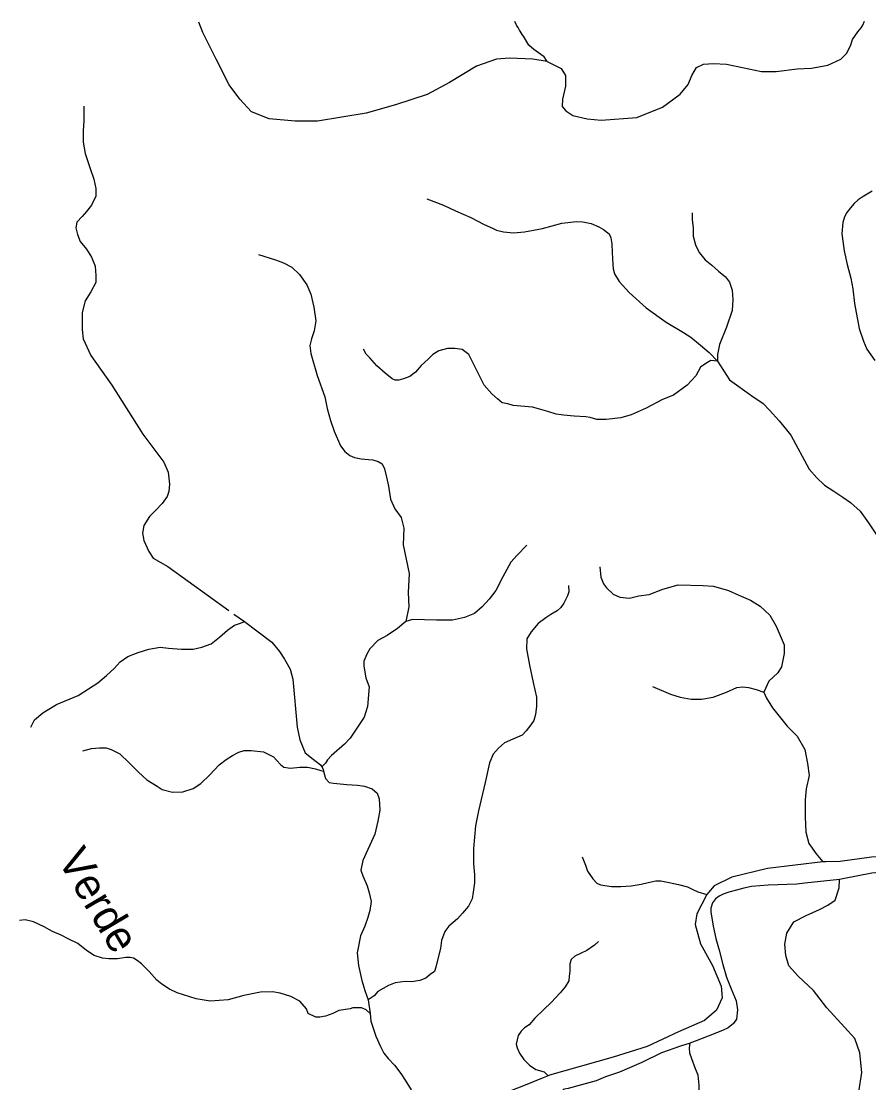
# Model space of a CAD drawing. Extents: x 436.3 to 500.4, y 8231 to 8286.4.
# Drawn here: x 467.97 to 473.38, y 8279.55 to 8286.33 of the extents above; entities that cross this region are included whole.
import ezdxf
from ezdxf.enums import TextEntityAlignment as Align

# ---------------------------------------------------------------- set-up
doc = ezdxf.new("R2010")
doc.units = 0
doc.header["$LTSCALE"] = 0.08
doc.linetypes.add('LONG_DASHED', pattern=[7.5, 6, -1.5])
for name, color, linetype, lineweight in [('2', 7, 'Continuous', 25), ('7', 7, 'Continuous', 25), ('9', 7, 'LONG_DASHED', 25)]:
    doc.layers.add(name, color=color, linetype=linetype, lineweight=lineweight)
doc.layers.add('61', color=7, linetype='Continuous')

msp = doc.modelspace()

# ---------------------------------------------------------------- linework, layer by layer
at = {"layer": '2'}
for points in [[(474.3305, 8281.4045), (474.2809, 8281.3357), (474.1471, 8281.1798), (474.058, 8281.1131), (473.9298, 8281.063), (473.8071, 8281.0295), (473.5859, 8281.0006), (473.4019, 8280.9949), (473.2012, 8280.9669), (473.1097, 8280.965), (473.0916, 8280.9642)], [(474.3152, 8281.2109), (474.2672, 8281.1647), (474.2064, 8281.1116), (474.1321, 8281.0507), (474.0522, 8281.0127), (473.9494, 8280.9767), (473.8485, 8280.9481), (473.6818, 8280.9216), (473.5485, 8280.9044), (473.4038, 8280.8911), (473.2198, 8280.8552), (473.1971, 8280.8509)], [(473.0916, 8280.9642), (472.7382, 8280.9222), (472.5097, 8280.8664), (472.3983, 8280.8106), (472.3612, 8280.7687), (472.3504, 8280.7564)], [(473.1971, 8280.8509), (472.9763, 8280.8278), (472.9249, 8280.822), (472.7422, 8280.8142), (472.6356, 8280.8066), (472.588, 8280.7951), (472.5404, 8280.7837), (472.4909, 8280.7704), (472.4548, 8280.7571), (472.43, 8280.7457)], [(472.3504, 8280.7564), (472.287, 8280.6324), (472.2761, 8280.5632), (472.3097, 8280.4407), (472.388, 8280.3016), (472.4427, 8280.1693), (472.4479, 8280.0954), (472.4123, 8280.0166), (472.3361, 8279.9506), (472.171, 8279.8785), (471.9705, 8279.7838), (471.7531, 8279.717), (471.3466, 8279.6007), (471.3388, 8279.5975)], [(472.43, 8280.7457), (472.4054, 8280.7286), (472.3882, 8280.702), (472.3769, 8280.6678), (472.377, 8280.6454), (472.3904, 8280.5523), (472.4076, 8280.4744)], [(472.4076, 8280.4744), (472.4287, 8280.4003), (472.4536, 8280.3091), (472.4766, 8280.2275), (472.5068, 8280.1521), (472.5374, 8280.0762), (472.5469, 8280.0192), (472.5394, 8279.9585), (472.5222, 8279.9319), (472.4862, 8279.9034), (472.45, 8279.8863), (472.3586, 8279.85), (472.2826, 8279.8205), (472.2536, 8279.8109), (472.2478, 8279.8075), (472.2446, 8279.8065)], [(472.2446, 8279.8065), (472.1836, 8279.7872), (472.0606, 8279.7445), (471.9351, 8279.6818), (471.7925, 8279.6211), (471.7049, 8279.5907), (471.6441, 8279.5659), (471.5508, 8279.5393), (471.4662, 8279.517), (471.4429, 8279.5118), (471.4344, 8279.5086), (471.4339, 8279.5085), (471.4311, 8279.5077)], [(471.3388, 8279.5975), (471.3373, 8279.5969), (471.307, 8279.5845), (471.1919, 8279.5375), (470.9078, 8279.4262), (470.6906, 8279.3427), (470.5717, 8279.309), (470.5428, 8279.3005)]]:
    msp.add_lwpolyline(points, dxfattribs=at)
at = {"layer": '7'}
for points in [[(470.2005, 8279.9953), (470.1763, 8280.0194), (470.1459, 8280.0315), (470.0915, 8280.0315), (470.0733, 8280.0255), (470.0005, 8280.0134), (469.9642, 8279.9953), (469.9157, 8279.9771), (469.8794, 8279.9711), (469.8551, 8279.9711), (469.8066, 8279.9952), (469.7944, 8280.0255), (469.7519, 8280.0739), (469.6959, 8280.1042), (469.6261, 8280.1253), (469.5776, 8280.1344), (469.5019, 8280.1314), (469.3959, 8280.1102), (469.2959, 8280.0829), (469.1809, 8280.0737), (469.0899, 8280.0888), (468.9702, 8280.1281), (468.9207, 8280.1505), (468.8712, 8280.182), (468.8396, 8280.2089), (468.7901, 8280.2629), (468.7406, 8280.3123), (468.7136, 8280.3348), (468.6911, 8280.3483), (468.6686, 8280.3528), (468.6416, 8280.3527), (468.5877, 8280.3437), (468.5337, 8280.3436), (468.4933, 8280.3481), (468.4393, 8280.366), (468.3898, 8280.3975), (468.3358, 8280.4424), (468.2773, 8280.4693), (468.2278, 8280.4963), (468.1738, 8280.5187), (468.1192, 8280.5479), (468.0525, 8280.5811), (467.998, 8280.5933), (467.9616, 8280.5901)], [(470.2005, 8279.9953), (470.2067, 8279.9468), (470.2371, 8279.8499), (470.2675, 8279.7834), (470.2883, 8279.7416), (470.3163, 8279.7073), (470.3558, 8279.6651), (470.3964, 8279.6112), (470.4254, 8279.5694), (470.464, 8279.5078), (470.4911, 8279.4538), (470.5136, 8279.3954), (470.5398, 8279.309), (470.5428, 8279.3005)]]:
    msp.add_lwpolyline(points, dxfattribs=at)
at = {"layer": '9'}
for points in [[(469.1441, 8286.2409), (469.1337, 8286.2631), (469.1073, 8286.3294)], [(471.3308, 8286.0766), (471.3133, 8286.1064), (471.2911, 8286.1229), (471.2468, 8286.1532), (471.2136, 8286.1808), (471.1804, 8286.2386), (471.1728, 8286.2489), (471.1602, 8286.2704), (471.1554, 8286.2775), (471.1454, 8286.295), (471.1385, 8286.3061), (471.1256, 8286.332)], [(471.3308, 8286.0766), (471.4208, 8286.0319), (471.4489, 8285.9879), (471.4489, 8285.919), (471.4284, 8285.8376), (471.4268, 8285.7899), (471.4509, 8285.7629), (471.496, 8285.733), (471.5861, 8285.7105), (471.6762, 8285.703), (471.9035, 8285.7187), (472.0687, 8285.786), (472.1813, 8285.8681), (472.2322, 8285.9307), (472.2543, 8285.9885), (472.2848, 8286.0381), (472.329, 8286.0602), (472.3927, 8286.0656), (472.4757, 8286.0601), (472.5782, 8286.0381), (472.6999, 8286.0133), (472.7941, 8286.0133), (472.9269, 8286.0298), (473.0184, 8286.0353), (473.1235, 8286.0546), (473.2066, 8286.0931), (473.2454, 8286.1317), (473.2703, 8286.184), (473.2813, 8286.217), (473.3145, 8286.2666), (473.3353, 8286.2935), (473.3464, 8286.3089), (473.3579, 8286.3347)], [(471.3308, 8286.0766), (471.2406, 8286.0916), (471.0905, 8286.0991), (471.0079, 8286.0916), (470.8804, 8286.0468), (470.7077, 8285.9423), (470.5652, 8285.8675), (470.3626, 8285.8004), (470.175, 8285.7481), (469.8646, 8285.6958), (469.722, 8285.6958), (469.5569, 8285.7107), (469.4444, 8285.7556), (469.3693, 8285.8377), (469.3018, 8285.9273), (469.2191, 8286.0915), (469.1441, 8286.2409)], [(468.3735, 8285.7916), (468.3736, 8285.6992), (468.3695, 8285.6348), (468.3695, 8285.5625), (468.3818, 8285.4901), (468.4141, 8285.3936), (468.4383, 8285.3252), (468.4504, 8285.265), (468.4504, 8285.2167), (468.4223, 8285.1604), (468.39, 8285.1201), (468.3618, 8285.088), (468.3294, 8285.0518), (468.3215, 8285.0155), (468.3336, 8284.9712), (468.3497, 8284.9271), (468.3901, 8284.8787), (468.4225, 8284.8265), (468.4467, 8284.7701), (468.4508, 8284.7098), (468.4508, 8284.6655), (468.4186, 8284.6051), (468.3824, 8284.5488), (468.3617, 8284.4735), (468.3618, 8284.3649), (468.3699, 8284.3045), (468.4185, 8284.1997), (468.5519, 8284.0104), (468.7502, 8283.696), (468.827, 8283.5953), (468.8837, 8283.5186), (468.9121, 8283.4541), (468.9202, 8283.3775), (468.917, 8283.3309), (468.905, 8283.2987), (468.8728, 8283.2543), (468.8325, 8283.2099), (468.7922, 8283.1696), (468.7559, 8283.1131), (468.7479, 8283.0647), (468.7561, 8283.0163), (468.7885, 8282.9477), (468.8168, 8282.9033), (468.9097, 8282.8509), (469.3312, 8282.5461), (469.399, 8282.5001)], [(473.406, 8285.2483), (473.3434, 8285.2108), (473.3162, 8285.1942), (473.2912, 8285.1692), (473.2682, 8285.1422), (473.2452, 8285.1131), (473.2306, 8285.086), (473.2203, 8285.0485), (473.2119, 8284.9757), (473.2287, 8284.8675), (473.2476, 8284.7801), (473.2706, 8284.6934), (473.2832, 8284.6246), (473.2938, 8284.531), (473.3231, 8284.3707), (473.3505, 8284.2902), (473.3735, 8284.2402), (473.4238, 8284.1673)], [(470.5639, 8285.1993), (470.6691, 8285.1589), (470.7461, 8285.1227), (470.8432, 8285.0803), (470.9302, 8285.036), (470.9828, 8285.0118), (471.0091, 8284.9996), (471.0536, 8284.9896), (471.1163, 8284.9836), (471.1871, 8284.9895), (471.3024, 8285.0096), (471.4258, 8285.0439), (471.5199, 8285.0558), (471.5583, 8285.0538), (471.613, 8285.0417), (471.6616, 8285.0215), (471.6919, 8285.0033), (471.7283, 8284.9771), (471.7385, 8284.951), (471.7446, 8284.9126), (471.7466, 8284.8582), (471.7508, 8284.7815), (471.7528, 8284.7534), (471.7609, 8284.7211), (471.7913, 8284.6727), (471.8541, 8284.6021), (471.9642, 8284.5041), (472.0917, 8284.4113), (472.201, 8284.3468), (472.2496, 8284.3165), (472.3103, 8284.2661), (472.3651, 8284.2176), (472.4183, 8284.1638)], [(472.2566, 8285.1109), (472.2566, 8285.0655), (472.2637, 8285.0167), (472.2637, 8284.9609), (472.2778, 8284.9051), (472.3023, 8284.8562), (472.3408, 8284.8109), (472.3829, 8284.776), (472.4249, 8284.7377), (472.4705, 8284.7027), (472.495, 8284.6679), (472.5126, 8284.6156), (472.5161, 8284.5562), (472.5127, 8284.4864), (472.4775, 8284.3801), (472.4322, 8284.2685), (472.4182, 8284.2056), (472.4183, 8284.1638)], [(469.488, 8284.8438), (469.5974, 8284.8095), (469.6475, 8284.7908), (469.7006, 8284.7628), (469.7507, 8284.716), (469.7977, 8284.6505), (469.8227, 8284.5913), (469.8415, 8284.5072), (469.8542, 8284.4199), (469.8448, 8284.3575), (469.8261, 8284.3045), (469.8167, 8284.264), (469.8231, 8284.2109), (469.8639, 8284.0707), (469.9112, 8283.9343), (469.927, 8283.8594), (469.949, 8283.7845), (469.971, 8283.7159), (470.0117, 8283.6223), (470.0399, 8283.5848), (470.0712, 8283.5598), (470.1025, 8283.5473), (470.1432, 8283.538), (470.1901, 8283.5348), (470.2182, 8283.5317), (470.2526, 8283.5224), (470.2776, 8283.5067), (470.2934, 8283.4755), (470.3059, 8283.4224), (470.3185, 8283.3632), (470.3311, 8283.2819), (470.3593, 8283.2196), (470.4001, 8283.1634), (470.4161, 8283.096), (470.4132, 8282.9899), (470.451, 8282.8056), (470.4449, 8282.6839), (470.4482, 8282.5933), (470.4291, 8282.5003)], [(470.3415, 8284.0495), (470.297, 8284.0856), (470.2431, 8284.1332), (470.1986, 8284.1838), (470.1764, 8284.2076), (470.1588, 8284.2392)], [(470.8314, 8284.2046), (470.7892, 8284.2373), (470.7411, 8284.2435), (470.6951, 8284.2435), (470.6404, 8284.2291), (470.602, 8284.2065), (470.5714, 8284.1747), (470.5276, 8284.1357), (470.4904, 8284.0936), (470.4542, 8284.0649), (470.4148, 8284.0495), (470.3853, 8284.0413), (470.3612, 8284.0423), (470.3415, 8284.0495)], [(472.4183, 8284.1638), (472.376, 8284.1663), (472.3445, 8284.1488), (472.3096, 8284.1245), (472.2816, 8284.0687), (472.2256, 8284.0093), (472.1382, 8283.9465), (472.0682, 8283.9186), (471.9633, 8283.8627), (471.8689, 8283.8209), (471.8024, 8283.8), (471.7079, 8283.7895), (471.6484, 8283.7895), (471.6063, 8283.8035), (471.5783, 8283.807), (471.5049, 8283.8105), (471.4349, 8283.8175), (471.3894, 8283.8246), (471.3357, 8283.8414), (471.2762, 8283.8589), (471.2378, 8283.8694), (471.1153, 8283.88), (471.0802, 8283.8905), (471.0452, 8283.8975), (471.0137, 8283.9219), (470.9787, 8283.9533), (470.9296, 8284.0092), (470.8735, 8284.1209), (470.8314, 8284.2046)], [(472.4183, 8284.1638), (472.4953, 8284.0429), (472.6391, 8283.9419), (472.7099, 8283.8914), (472.7505, 8283.8491), (472.8133, 8283.7825), (472.8862, 8283.6897), (473.005, 8283.4728), (473.0541, 8283.4169), (473.1031, 8283.3716), (473.1627, 8283.3331), (473.2187, 8283.2947), (473.2678, 8283.2598), (473.3309, 8283.2039), (473.3835, 8283.1306), (473.4817, 8282.9839)], [(471.2019, 8282.987), (471.139, 8282.9243), (471.1006, 8282.8789), (471.0483, 8282.7846), (471.003, 8282.6973), (470.9611, 8282.6414), (470.9156, 8282.5926), (470.8668, 8282.5507), (470.8039, 8282.5262), (470.727, 8282.5088), (470.6256, 8282.5089), (470.4717, 8282.5124), (470.4291, 8282.5003)], [(471.6673, 8282.8495), (471.6752, 8282.7837), (471.6908, 8282.741), (471.7102, 8282.7139), (471.753, 8282.6752), (471.7957, 8282.6558), (471.8577, 8282.6481), (471.9159, 8282.6636), (471.9819, 8282.6713), (472.0711, 8282.7062), (472.168, 8282.7332), (472.3271, 8282.7293), (472.393, 8282.7255), (472.4901, 8282.6983), (472.5561, 8282.6673), (472.6299, 8282.6363), (472.692, 8282.5977), (472.7542, 8282.5396), (472.7931, 8282.4698), (472.8437, 8282.3498), (472.8437, 8282.2956), (472.8284, 8282.2103), (472.8051, 8282.1717), (472.747, 8282.1174), (472.7154, 8282.0484)], [(471.4675, 8282.7289), (471.4699, 8282.6883), (471.4618, 8282.6642), (471.4378, 8282.616), (471.4191, 8282.5892), (471.395, 8282.5678), (471.3548, 8282.5438), (471.3228, 8282.5224), (471.2745, 8282.4876), (471.2291, 8282.4341), (471.2024, 8282.3886), (471.1998, 8282.3243), (471.2186, 8282.2201), (471.243, 8282.1103), (471.2645, 8282.0152), (471.2645, 8281.9589), (471.2566, 8281.9054), (471.246, 8281.8679), (471.2272, 8281.8385), (471.1978, 8281.801), (471.1711, 8281.7743), (471.1122, 8281.7475), (471.0587, 8281.7234), (471.0212, 8281.6913), (470.9864, 8281.6511), (470.9624, 8281.5976), (470.9358, 8281.4718), (470.8927, 8281.2906), (470.8742, 8281.1942), (470.861, 8281.0498), (470.8612, 8280.9508), (470.8666, 8280.8812), (470.8667, 8280.8303), (470.8588, 8280.7714), (470.8527, 8280.7268), (470.8287, 8280.6813), (470.7913, 8280.6358), (470.7592, 8280.601), (470.703, 8280.5529), (470.6789, 8280.5181), (470.6576, 8280.4619), (470.6496, 8280.4111), (470.631, 8280.3361), (470.6204, 8280.2907), (470.6123, 8280.2639), (470.5856, 8280.2452), (470.5562, 8280.2211), (470.5187, 8280.2051), (470.4678, 8280.197), (470.4249, 8280.1997), (470.3607, 8280.1917), (470.3178, 8280.173), (470.2509, 8280.1356), (470.2269, 8280.1088), (470.1882, 8280.0826)], [(468.0341, 8281.8249), (468.0584, 8281.8704), (468.1107, 8281.9158), (468.1979, 8281.9684), (468.3375, 8282.0279), (468.4039, 8282.0699), (468.4631, 8282.1084), (468.519, 8282.1539), (468.5679, 8282.1993), (468.6061, 8282.2413), (468.655, 8282.2762), (468.7213, 8282.3007), (468.7877, 8282.3218), (468.8611, 8282.3357), (468.9135, 8282.3287), (468.9974, 8282.3219), (469.0708, 8282.3219), (469.1267, 8282.3358), (469.1861, 8282.3568), (469.2385, 8282.3987), (469.2908, 8282.4441), (469.3362, 8282.4756), (469.3746, 8282.4896), (469.399, 8282.5001)], [(469.399, 8282.5001), (469.5738, 8282.3686), (469.6222, 8282.3081), (469.6547, 8282.2597), (469.6911, 8282.1951), (469.7074, 8282.1304), (469.7362, 8281.8238), (469.7525, 8281.7431), (469.7856, 8281.6607), (469.8382, 8281.6203), (469.8837, 8281.5848), (469.8927, 8281.5704)], [(470.4291, 8282.5003), (470.3766, 8282.4549), (470.3102, 8282.4096), (470.2509, 8282.3782), (470.1985, 8282.3258), (470.1811, 8282.2908), (470.1602, 8282.2454), (470.1603, 8282.214), (470.1743, 8282.1406), (470.1954, 8282.0812), (470.1851, 8281.9555), (470.164, 8281.8878), (470.0733, 8281.7551), (470.0384, 8281.7167), (469.9547, 8281.6433), (469.93, 8281.6148), (469.916, 8281.5941), (469.8927, 8281.5704)], [(472.0038, 8282.0854), (472.1191, 8282.0361), (472.1807, 8282.0156), (472.2506, 8282.0032), (472.3164, 8282.0032), (472.3905, 8282.0156), (472.4768, 8282.0484), (472.5426, 8282.0772), (472.5796, 8282.0813), (472.6166, 8282.0772), (472.666, 8282.0648), (472.7154, 8282.0484)], [(472.7154, 8282.0484), (472.7316, 8282.009), (472.7705, 8281.947), (472.8638, 8281.8308), (472.9269, 8281.7665), (472.9775, 8281.6814), (472.9931, 8281.5922), (473.0049, 8281.5148), (472.9856, 8281.4296), (472.9779, 8281.3599), (472.9781, 8281.2514), (472.9821, 8281.1546), (473.0016, 8281.081), (473.0483, 8281.0152), (473.0916, 8280.9642)], [(468.3661, 8281.6739), (468.422, 8281.688), (468.4744, 8281.6915), (468.5163, 8281.6915), (468.5478, 8281.6811), (468.6037, 8281.6531), (468.6633, 8281.5972), (468.7227, 8281.538), (468.7753, 8281.4891), (468.8418, 8281.4471), (468.8732, 8281.4262), (468.9397, 8281.4088), (469.006, 8281.4123), (469.0724, 8281.4333), (469.1212, 8281.4648), (469.1771, 8281.5207), (469.2364, 8281.5836), (469.2817, 8281.6185), (469.3236, 8281.6431), (469.3621, 8281.664), (469.3969, 8281.6745), (469.4424, 8281.6745), (469.5209, 8281.6673), (469.5839, 8281.6359), (469.6049, 8281.6114), (469.6295, 8281.587), (469.6504, 8281.5695), (469.6924, 8281.5625), (469.7518, 8281.5695), (469.8007, 8281.5695), (469.8532, 8281.559), (469.8865, 8281.5478), (469.9046, 8281.543)], [(469.8927, 8281.5704), (469.9013, 8281.5568), (469.9046, 8281.543)], [(469.9046, 8281.543), (469.9158, 8281.4969), (469.9397, 8281.4701), (469.9677, 8281.467), (470.0525, 8281.4589), (470.1212, 8281.4549), (470.1655, 8281.4468), (470.2141, 8281.4307), (470.2464, 8281.4024), (470.2586, 8281.3661), (470.2628, 8281.2935), (470.2508, 8281.2249), (470.2308, 8281.1401), (470.1543, 8280.9723), (470.1423, 8280.9118), (470.1544, 8280.8755), (470.1828, 8280.8109), (470.195, 8280.7665), (470.2072, 8280.71), (470.1993, 8280.6535), (470.1872, 8280.6092), (470.1671, 8280.5527), (470.139, 8280.4922), (470.1229, 8280.4035), (470.119, 8280.3833), (470.1271, 8280.3026), (470.1474, 8280.2058), (470.1677, 8280.1413), (470.1882, 8280.0826), (470.2005, 8279.9953)], [(471.555, 8280.9956), (471.576, 8280.9422), (471.59, 8280.905), (471.6226, 8280.8562), (471.6482, 8280.8284), (471.6716, 8280.8167), (471.7414, 8280.8075), (471.8018, 8280.8076), (471.867, 8280.8099), (471.932, 8280.8215), (471.9762, 8280.8331), (472.025, 8280.8424), (472.0576, 8280.8424), (472.1111, 8280.8331), (472.1692, 8280.8192), (472.2275, 8280.8053), (472.2624, 8280.7867), (472.2926, 8280.7728), (472.3504, 8280.7564)], [(473.3211, 8279.4952), (473.3405, 8279.6175), (473.3279, 8279.7442), (473.295, 8279.8357), (473.2293, 8279.9077), (473.1176, 8280.0318), (473.0322, 8280.143), (472.9337, 8280.2345), (472.8746, 8280.3), (472.8548, 8280.3654), (472.8482, 8280.4373), (472.8612, 8280.5094), (472.907, 8280.5815), (472.9857, 8280.6208), (473.0709, 8280.6601), (473.1233, 8280.6864), (473.1693, 8280.7191), (473.1954, 8280.7977), (473.1971, 8280.8509)], [(471.6601, 8280.4555), (471.6329, 8280.4313), (471.5846, 8280.3981), (471.5482, 8280.3799), (471.509, 8280.3619), (471.4848, 8280.3407), (471.4757, 8280.3135), (471.4758, 8280.2682), (471.4729, 8280.2319), (471.4699, 8280.2047), (471.4458, 8280.1654), (471.4155, 8280.1262), (471.3581, 8280.0658), (471.3098, 8280.0205), (471.2524, 8279.9661), (471.2161, 8279.9238), (471.1859, 8279.9027), (471.1647, 8279.8816), (471.1466, 8279.8544), (471.1406, 8279.8272), (471.1346, 8279.8001), (471.1407, 8279.7759), (471.1558, 8279.7426), (471.1831, 8279.7003), (471.2195, 8279.6642), (471.2588, 8279.637), (471.3133, 8279.6218), (471.3388, 8279.5975)], [(472.3052, 8279.4479), (472.3017, 8279.538), (472.295, 8279.6013), (472.2783, 8279.6412), (472.2548, 8279.7046), (472.2414, 8279.7413), (472.24, 8279.7761), (472.2446, 8279.8065)]]:
    msp.add_lwpolyline(points, dxfattribs=at)

# ---------------------------------------------------------------- texts
at = {"layer": '61'}
msp.add_text('Córrego           Verde', height=0.2, rotation=300.627, dxfattribs=at).set_placement((467.9292, 8281.4382), align=Align.CENTER)

doc.saveas('drawing.dxf')
